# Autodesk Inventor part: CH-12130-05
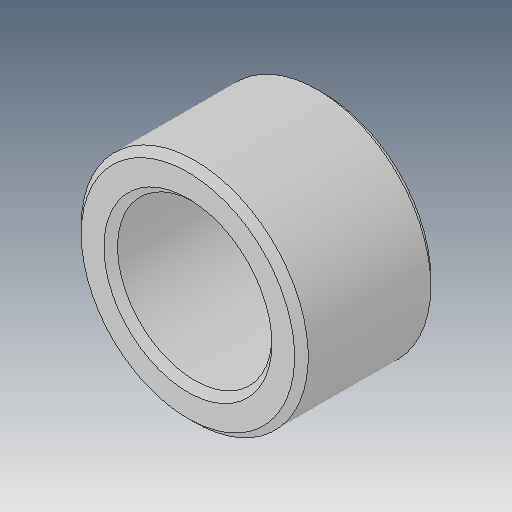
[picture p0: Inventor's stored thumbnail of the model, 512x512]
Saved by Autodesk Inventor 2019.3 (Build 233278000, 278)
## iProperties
Created: 2012-09
Part Number: CH-12130-05
Material: Ogólny
Document SubType Name: Modeling
Designer: CADENGINEERING4
Density: 1 g/cm^3
Appearance: Domyślna
Author: CADENGINEERING4
Revision Number: ÈÎºÎ
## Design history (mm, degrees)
feature "µ¹½Ç1"
node "Bryła1"
